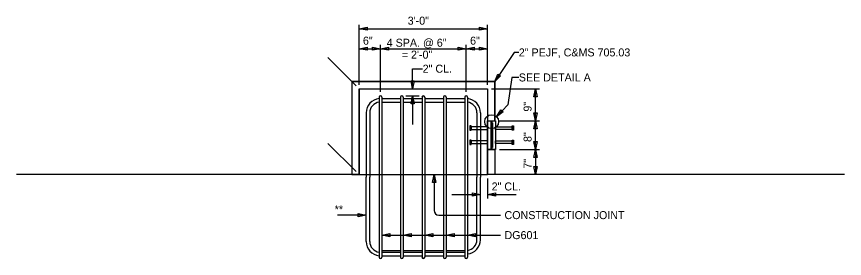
# Model space of a CAD drawing. Extents: x 1542883 to 1543620, y 586895 to 587380.
# Drawn here: x 1543043.59 to 1543058.08, y 587131.11 to 587135.34 of the extents above; entities that cross this region are included whole.
import ezdxf

# ---------------------------------------------------------------- set-up
doc = ezdxf.new("R2010")
doc.units = 0
for name, color, linetype in [('BR_P_Dia_Stl_Det', 7, 'Continuous'), ('BR_P_Gen_Text', 7, 'Continuous'), ('ST_Details', 7, 'Continuous'), ('ST_Text', 7, 'Continuous')]:
    doc.layers.add(name, color=color, linetype=linetype)

msp = doc.modelspace()

# ---------------------------------------------------------------- linework, layer by layer
at = {"layer": 'BR_P_Dia_Stl_Det'}
for p, q in [((1543049.582, 587134.151), (1543049.582, 587135.201)), ((1543049.582, 587135.131), (1543051.832, 587135.131)), ((1543051.832, 587134.151), (1543051.832, 587135.201)), ((1543049.957, 587134.026), (1543049.957, 587134.851)), ((1543051.457, 587134.026), (1543051.457, 587134.851)), ((1543049.582, 587134.781), (1543049.957, 587134.781)), ((1543049.957, 587134.781), (1543051.457, 587134.781)), ((1543051.457, 587134.781), (1543051.832, 587134.781)), ((1543049.533, 587134.13), (1543049.038, 587134.625)), ((1543050.52, 587134.081), (1543050.52, 587134.431)), ((1543050.52, 587134.431), (1543050.695, 587134.431)), ((1543052.257, 587134.278), (1543052.187, 587133.801)), ((1543052.378, 587134.278), (1543052.257, 587134.278)), ((1543049.457, 587134.206), (1543049.457, 587132.581)), ((1543049.457, 587134.206), (1543051.957, 587134.206)), ((1543051.957, 587134.206), (1543051.957, 587133.518)), ((1543049.582, 587134.081), (1543051.832, 587134.081)), ((1543049.582, 587134.081), (1543049.582, 587132.581)), ((1543051.832, 587134.081), (1543051.832, 587132.581)), ((1543051.902, 587134.081), (1543052.741, 587134.081)), ((1543052.671, 587133.518), (1543052.671, 587134.081)), ((1543049.934, 587133.932), (1543049.934, 587131.136)), ((1543049.981, 587133.932), (1543049.981, 587131.136)), ((1543049.981, 587133.909), (1543050.309, 587133.909)), ((1543049.981, 587133.847), (1543050.309, 587133.847)), ((1543050.309, 587133.932), (1543050.309, 587131.136)), ((1543050.356, 587133.932), (1543050.356, 587131.136)), ((1543050.356, 587133.909), (1543050.684, 587133.909)), ((1543050.356, 587133.847), (1543050.684, 587133.847)), ((1543050.402, 587133.956), (1543050.637, 587133.956)), ((1543050.52, 587133.956), (1543050.52, 587133.456)), ((1543050.684, 587133.932), (1543050.684, 587131.136)), ((1543050.731, 587133.932), (1543050.731, 587131.136)), ((1543050.731, 587133.909), (1543051.059, 587133.909)), ((1543050.731, 587133.847), (1543051.059, 587133.847)), ((1543051.059, 587133.932), (1543051.059, 587131.136)), ((1543051.106, 587133.932), (1543051.106, 587131.136)), ((1543051.106, 587133.909), (1543051.434, 587133.909)), ((1543051.106, 587133.847), (1543051.434, 587133.847)), ((1543051.434, 587133.932), (1543051.434, 587131.136)), ((1543051.481, 587133.932), (1543051.481, 587131.136)), ((1543052.187, 587133.801), (1543051.987, 587133.592)), ((1543049.707, 587133.659), (1543049.707, 587132.534)), ((1543049.77, 587133.659), (1543049.77, 587132.534)), ((1543051.645, 587133.659), (1543051.645, 587132.534)), ((1543051.707, 587133.659), (1543051.707, 587132.534)), ((1543051.908, 587133.487), (1543051.908, 587133.518)), ((1543052.041, 587133.518), (1543052.741, 587133.518)), ((1543052.671, 587133.018), (1543052.671, 587133.518)), ((1543049.533, 587132.63), (1543049.038, 587133.125)), ((1543051.908, 587133.05), (1543051.908, 587133.018)), ((1543051.957, 587133.018), (1543051.957, 587132.581)), ((1543052.041, 587133.018), (1543052.741, 587133.018)), ((1543052.671, 587133.018), (1543052.671, 587132.581)), ((1543049.582, 587132.581), (1543043.59, 587132.581)), ((1543049.582, 587132.581), (1543051.832, 587132.581)), ((1543049.707, 587131.409), (1543049.707, 587132.534)), ((1543049.77, 587131.409), (1543049.77, 587132.534)), ((1543050.895, 587132.581), (1543050.895, 587131.953)), ((1543051.645, 587131.44), (1543051.645, 587132.534)), ((1543051.707, 587131.44), (1543051.707, 587132.534)), ((1543058.075, 587132.581), (1543051.832, 587132.581)), ((1543051.832, 587132.511), (1543051.832, 587132.161)), ((1543051.207, 587132.231), (1543051.707, 587132.231)), ((1543051.832, 587132.231), (1543052.332, 587132.231)), ((1543049.707, 587131.87), (1543049.207, 587131.87)), ((1543050.978, 587131.87), (1543052.057, 587131.87)), ((1543049.981, 587131.52), (1543052.057, 587131.52)), ((1543049.981, 587131.253), (1543050.309, 587131.253)), ((1543049.981, 587131.222), (1543050.309, 587131.222)), ((1543050.356, 587131.253), (1543050.684, 587131.253)), ((1543050.356, 587131.222), (1543050.684, 587131.222)), ((1543050.731, 587131.253), (1543051.059, 587131.253)), ((1543050.731, 587131.222), (1543051.059, 587131.222)), ((1543051.106, 587131.253), (1543051.434, 587131.253)), ((1543051.106, 587131.222), (1543051.434, 587131.222)), ((1543049.981, 587131.159), (1543050.309, 587131.159)), ((1543050.356, 587131.159), (1543050.684, 587131.159)), ((1543050.731, 587131.159), (1543051.059, 587131.159)), ((1543051.106, 587131.159), (1543051.434, 587131.159))]:
    msp.add_line(p, q, dxfattribs=at)
for points in [[(1543049.722, 587135.159), (1543049.722, 587135.103), (1543049.582, 587135.131)], [(1543051.692, 587135.103), (1543051.692, 587135.159), (1543051.832, 587135.131)], [(1543049.722, 587134.809), (1543049.722, 587134.753), (1543049.582, 587134.781)], [(1543049.817, 587134.753), (1543049.817, 587134.809), (1543049.957, 587134.781)], [(1543050.097, 587134.809), (1543050.097, 587134.753), (1543049.957, 587134.781)], [(1543051.317, 587134.753), (1543051.317, 587134.809), (1543051.457, 587134.781)], [(1543051.597, 587134.809), (1543051.597, 587134.753), (1543051.457, 587134.781)], [(1543051.692, 587134.753), (1543051.692, 587134.809), (1543051.832, 587134.781)], [(1543052.012, 587134.338), (1543052.059, 587134.307), (1543051.957, 587134.206)], [(1543049.457, 587132.581), (1543049.582, 587132.581), (1543049.582, 587134.081), (1543051.832, 587134.081), (1543051.832, 587133.518), (1543051.957, 587133.518), (1543051.957, 587134.206), (1543049.457, 587134.206)], [(1543050.492, 587134.221), (1543050.548, 587134.221), (1543050.52, 587134.081)], [(1543052.699, 587133.941), (1543052.643, 587133.941), (1543052.671, 587134.081)], [(1543050.548, 587133.816), (1543050.492, 587133.816), (1543050.52, 587133.956)], [(1543052.063, 587133.713), (1543052.104, 587133.674), (1543051.987, 587133.592)], [(1543052.643, 587133.658), (1543052.699, 587133.658), (1543052.671, 587133.518)], [(1543051.543, 587133.432), (1543051.52, 587133.432), (1543051.52, 587133.354), (1543051.543, 587133.354)], [(1543051.832, 587133.417), (1543051.543, 587133.417), (1543051.543, 587133.37), (1543051.832, 587133.37)], [(1543051.832, 587133.518), (1543051.895, 587133.518), (1543051.895, 587133.018), (1543051.832, 587133.018)], [(1543051.895, 587133.518), (1543051.908, 587133.518), (1543051.908, 587133.487), (1543051.901, 587133.487), (1543051.901, 587133.503), (1543051.895, 587133.503)], [(1543051.895, 587133.503), (1543051.901, 587133.503), (1543051.901, 587133.034), (1543051.895, 587133.034)], [(1543051.901, 587133.487), (1543051.916, 587133.487), (1543051.916, 587133.05), (1543051.901, 587133.05)], [(1543051.971, 587133.417), (1543052.26, 587133.417), (1543052.26, 587133.37), (1543051.971, 587133.37)], [(1543052.26, 587133.432), (1543052.283, 587133.432), (1543052.283, 587133.354), (1543052.26, 587133.354)], [(1543052.699, 587133.378), (1543052.643, 587133.378), (1543052.671, 587133.518)], [(1543051.543, 587133.182), (1543051.52, 587133.182), (1543051.52, 587133.104), (1543051.543, 587133.104)], [(1543051.832, 587133.167), (1543051.543, 587133.167), (1543051.543, 587133.12), (1543051.832, 587133.12)], [(1543051.971, 587133.167), (1543052.26, 587133.167), (1543052.26, 587133.12), (1543051.971, 587133.12)], [(1543052.26, 587133.182), (1543052.283, 587133.182), (1543052.283, 587133.104), (1543052.26, 587133.104)], [(1543052.643, 587133.158), (1543052.699, 587133.158), (1543052.671, 587133.018)], [(1543051.832, 587132.581), (1543051.832, 587133.018), (1543051.957, 587133.018), (1543051.957, 587132.581)], [(1543052.699, 587132.878), (1543052.643, 587132.878), (1543052.671, 587133.018)], [(1543052.643, 587132.721), (1543052.699, 587132.721), (1543052.671, 587132.581)], [(1543050.923, 587132.441), (1543050.867, 587132.441), (1543050.895, 587132.581)], [(1543051.567, 587132.203), (1543051.567, 587132.259), (1543051.707, 587132.231)], [(1543051.972, 587132.259), (1543051.972, 587132.203), (1543051.832, 587132.231)], [(1543049.567, 587131.842), (1543049.567, 587131.898), (1543049.707, 587131.87)], [(1543050.121, 587131.548), (1543050.121, 587131.492), (1543049.981, 587131.52)], [(1543050.496, 587131.548), (1543050.496, 587131.492), (1543050.356, 587131.52)], [(1543050.871, 587131.548), (1543050.871, 587131.492), (1543050.731, 587131.52)], [(1543051.246, 587131.548), (1543051.246, 587131.492), (1543051.106, 587131.52)], [(1543051.621, 587131.548), (1543051.621, 587131.492), (1543051.481, 587131.52)]]:
    msp.add_lwpolyline(points, close=True, dxfattribs=at)
for points in [[(1543052.378, 587134.716), (1543052.299, 587134.716), (1543051.957, 587134.206)], [(1543051.908, 587133.487), (1543051.908, 587133.518), (1543051.971, 587133.518), (1543051.971, 587133.018), (1543051.908, 587133.018), (1543051.908, 587133.05)]]:
    msp.add_lwpolyline(points, dxfattribs=at)
msp.add_circle((1543051.903, 587133.505), 0.121, dxfattribs=at)
for centre, radius, start, end in [((1543049.957, 587133.659), 0.25, 95.3794, 180), ((1543049.957, 587133.659), 0.188, 97.1808, 180), ((1543049.957, 587133.932), 0.0234, 0, 180), ((1543050.332, 587133.932), 0.0234, 0, 180), ((1543050.707, 587133.932), 0.0234, 0, 180), ((1543051.082, 587133.932), 0.0234, 0, 180), ((1543051.457, 587133.932), 0.0234, 0, 180), ((1543051.457, 587133.659), 0.25, 360, 84.6206), ((1543051.457, 587133.659), 0.188, 0, 82.8192), ((1543050.978, 587131.953), 0.0833, 180, 270), ((1543049.957, 587131.409), 0.25, 180, 264.6206), ((1543049.957, 587131.409), 0.188, 180, 262.8192), ((1543051.457, 587131.44), 0.188, 277.1808, 360), ((1543051.457, 587131.44), 0.25, 275.3794, 360), ((1543049.957, 587131.136), 0.0234, 180, 0), ((1543050.332, 587131.136), 0.0234, 180, 0), ((1543050.707, 587131.136), 0.0234, 180, 0), ((1543051.082, 587131.136), 0.0234, 180, 0), ((1543051.457, 587131.136), 0.0234, 180, 0)]:
    msp.add_arc(centre, radius, start, end, dxfattribs=at)
at = {"layer": 'BR_P_Gen_Text'}
for points in [[(1543049.722, 587135.159), (1543049.722, 587135.103), (1543049.582, 587135.131)], [(1543051.692, 587135.103), (1543051.692, 587135.159), (1543051.832, 587135.131)], [(1543049.722, 587134.809), (1543049.722, 587134.753), (1543049.582, 587134.781)], [(1543049.817, 587134.753), (1543049.817, 587134.809), (1543049.957, 587134.781)], [(1543050.097, 587134.809), (1543050.097, 587134.753), (1543049.957, 587134.781)], [(1543051.317, 587134.753), (1543051.317, 587134.809), (1543051.457, 587134.781)], [(1543051.597, 587134.809), (1543051.597, 587134.753), (1543051.457, 587134.781)], [(1543051.692, 587134.753), (1543051.692, 587134.809), (1543051.832, 587134.781)], [(1543052.012, 587134.338), (1543052.059, 587134.307), (1543051.957, 587134.206)], [(1543050.492, 587134.221), (1543050.548, 587134.221), (1543050.52, 587134.081)], [(1543052.699, 587133.941), (1543052.643, 587133.941), (1543052.671, 587134.081)], [(1543050.548, 587133.816), (1543050.492, 587133.816), (1543050.52, 587133.956)], [(1543052.063, 587133.713), (1543052.104, 587133.674), (1543051.987, 587133.592)], [(1543052.643, 587133.658), (1543052.699, 587133.658), (1543052.671, 587133.518)], [(1543052.699, 587133.378), (1543052.643, 587133.378), (1543052.671, 587133.518)], [(1543052.643, 587133.158), (1543052.699, 587133.158), (1543052.671, 587133.018)], [(1543052.699, 587132.878), (1543052.643, 587132.878), (1543052.671, 587133.018)], [(1543052.643, 587132.721), (1543052.699, 587132.721), (1543052.671, 587132.581)], [(1543050.923, 587132.441), (1543050.867, 587132.441), (1543050.895, 587132.581)], [(1543051.567, 587132.203), (1543051.567, 587132.259), (1543051.707, 587132.231)], [(1543051.972, 587132.259), (1543051.972, 587132.203), (1543051.832, 587132.231)], [(1543049.567, 587131.842), (1543049.567, 587131.898), (1543049.707, 587131.87)], [(1543050.121, 587131.548), (1543050.121, 587131.492), (1543049.981, 587131.52)], [(1543050.496, 587131.548), (1543050.496, 587131.492), (1543050.356, 587131.52)], [(1543050.871, 587131.548), (1543050.871, 587131.492), (1543050.731, 587131.52)], [(1543051.246, 587131.548), (1543051.246, 587131.492), (1543051.106, 587131.52)], [(1543051.621, 587131.548), (1543051.621, 587131.492), (1543051.481, 587131.52)]]:
    msp.add_lwpolyline(points, close=True, dxfattribs=at)
at = {"layer": 'ST_Details'}
for p, q in [((1543049.582, 587134.151), (1543049.582, 587135.201)), ((1543049.582, 587135.131), (1543051.832, 587135.131)), ((1543051.832, 587134.151), (1543051.832, 587135.201)), ((1543049.957, 587134.026), (1543049.957, 587134.851)), ((1543051.457, 587134.026), (1543051.457, 587134.851)), ((1543049.582, 587134.781), (1543049.957, 587134.781)), ((1543049.957, 587134.781), (1543051.457, 587134.781)), ((1543051.457, 587134.781), (1543051.832, 587134.781)), ((1543049.533, 587134.13), (1543049.038, 587134.625)), ((1543050.52, 587134.081), (1543050.52, 587134.431)), ((1543050.52, 587134.431), (1543050.695, 587134.431)), ((1543052.257, 587134.278), (1543052.187, 587133.801)), ((1543052.378, 587134.278), (1543052.257, 587134.278)), ((1543049.457, 587134.206), (1543049.457, 587132.581)), ((1543049.457, 587134.206), (1543051.957, 587134.206)), ((1543051.957, 587134.206), (1543051.957, 587133.518)), ((1543049.582, 587134.081), (1543051.832, 587134.081)), ((1543049.582, 587134.081), (1543049.582, 587132.581)), ((1543051.832, 587134.081), (1543051.832, 587132.581)), ((1543051.902, 587134.081), (1543052.741, 587134.081)), ((1543052.671, 587133.518), (1543052.671, 587134.081)), ((1543049.934, 587133.932), (1543049.934, 587131.136)), ((1543049.981, 587133.932), (1543049.981, 587131.136)), ((1543049.981, 587133.909), (1543050.309, 587133.909)), ((1543049.981, 587133.847), (1543050.309, 587133.847)), ((1543050.309, 587133.932), (1543050.309, 587131.136)), ((1543050.356, 587133.932), (1543050.356, 587131.136)), ((1543050.356, 587133.909), (1543050.684, 587133.909)), ((1543050.356, 587133.847), (1543050.684, 587133.847)), ((1543050.402, 587133.956), (1543050.637, 587133.956)), ((1543050.52, 587133.956), (1543050.52, 587133.456)), ((1543050.684, 587133.932), (1543050.684, 587131.136)), ((1543050.731, 587133.932), (1543050.731, 587131.136)), ((1543050.731, 587133.909), (1543051.059, 587133.909)), ((1543050.731, 587133.847), (1543051.059, 587133.847)), ((1543051.059, 587133.932), (1543051.059, 587131.136)), ((1543051.106, 587133.932), (1543051.106, 587131.136)), ((1543051.106, 587133.909), (1543051.434, 587133.909)), ((1543051.106, 587133.847), (1543051.434, 587133.847)), ((1543051.434, 587133.932), (1543051.434, 587131.136)), ((1543051.481, 587133.932), (1543051.481, 587131.136)), ((1543052.187, 587133.801), (1543051.987, 587133.592)), ((1543049.707, 587133.659), (1543049.707, 587132.534)), ((1543049.77, 587133.659), (1543049.77, 587132.534)), ((1543051.645, 587133.659), (1543051.645, 587132.534)), ((1543051.707, 587133.659), (1543051.707, 587132.534)), ((1543051.908, 587133.487), (1543051.908, 587133.518)), ((1543052.041, 587133.518), (1543052.741, 587133.518)), ((1543052.671, 587133.018), (1543052.671, 587133.518)), ((1543049.533, 587132.63), (1543049.038, 587133.125)), ((1543051.908, 587133.05), (1543051.908, 587133.018)), ((1543051.957, 587133.018), (1543051.957, 587132.581)), ((1543052.041, 587133.018), (1543052.741, 587133.018)), ((1543052.671, 587133.018), (1543052.671, 587132.581)), ((1543049.582, 587132.581), (1543043.59, 587132.581)), ((1543049.582, 587132.581), (1543051.832, 587132.581)), ((1543049.707, 587131.409), (1543049.707, 587132.534)), ((1543049.77, 587131.409), (1543049.77, 587132.534)), ((1543050.895, 587132.581), (1543050.895, 587131.953)), ((1543051.645, 587131.44), (1543051.645, 587132.534)), ((1543051.707, 587131.44), (1543051.707, 587132.534)), ((1543058.075, 587132.581), (1543051.832, 587132.581)), ((1543051.832, 587132.511), (1543051.832, 587132.161)), ((1543051.207, 587132.231), (1543051.707, 587132.231)), ((1543051.832, 587132.231), (1543052.332, 587132.231)), ((1543049.707, 587131.87), (1543049.207, 587131.87)), ((1543050.978, 587131.87), (1543052.057, 587131.87)), ((1543049.981, 587131.52), (1543052.057, 587131.52)), ((1543049.981, 587131.253), (1543050.309, 587131.253)), ((1543049.981, 587131.222), (1543050.309, 587131.222)), ((1543050.356, 587131.253), (1543050.684, 587131.253)), ((1543050.356, 587131.222), (1543050.684, 587131.222)), ((1543050.731, 587131.253), (1543051.059, 587131.253)), ((1543050.731, 587131.222), (1543051.059, 587131.222)), ((1543051.106, 587131.253), (1543051.434, 587131.253)), ((1543051.106, 587131.222), (1543051.434, 587131.222)), ((1543049.981, 587131.159), (1543050.309, 587131.159)), ((1543050.356, 587131.159), (1543050.684, 587131.159)), ((1543050.731, 587131.159), (1543051.059, 587131.159)), ((1543051.106, 587131.159), (1543051.434, 587131.159))]:
    msp.add_line(p, q, dxfattribs=at)
for points in [[(1543052.378, 587134.716), (1543052.299, 587134.716), (1543051.957, 587134.206)], [(1543051.908, 587133.487), (1543051.908, 587133.518), (1543051.971, 587133.518), (1543051.971, 587133.018), (1543051.908, 587133.018), (1543051.908, 587133.05)]]:
    msp.add_lwpolyline(points, dxfattribs=at)
for points in [[(1543049.457, 587132.581), (1543049.582, 587132.581), (1543049.582, 587134.081), (1543051.832, 587134.081), (1543051.832, 587133.518), (1543051.957, 587133.518), (1543051.957, 587134.206), (1543049.457, 587134.206)], [(1543051.543, 587133.432), (1543051.52, 587133.432), (1543051.52, 587133.354), (1543051.543, 587133.354)], [(1543051.832, 587133.417), (1543051.543, 587133.417), (1543051.543, 587133.37), (1543051.832, 587133.37)], [(1543051.832, 587133.518), (1543051.895, 587133.518), (1543051.895, 587133.018), (1543051.832, 587133.018)], [(1543051.895, 587133.518), (1543051.908, 587133.518), (1543051.908, 587133.487), (1543051.901, 587133.487), (1543051.901, 587133.503), (1543051.895, 587133.503)], [(1543051.895, 587133.503), (1543051.901, 587133.503), (1543051.901, 587133.034), (1543051.895, 587133.034)], [(1543051.901, 587133.487), (1543051.916, 587133.487), (1543051.916, 587133.05), (1543051.901, 587133.05)], [(1543051.971, 587133.417), (1543052.26, 587133.417), (1543052.26, 587133.37), (1543051.971, 587133.37)], [(1543052.26, 587133.432), (1543052.283, 587133.432), (1543052.283, 587133.354), (1543052.26, 587133.354)], [(1543051.543, 587133.182), (1543051.52, 587133.182), (1543051.52, 587133.104), (1543051.543, 587133.104)], [(1543051.832, 587133.167), (1543051.543, 587133.167), (1543051.543, 587133.12), (1543051.832, 587133.12)], [(1543051.971, 587133.167), (1543052.26, 587133.167), (1543052.26, 587133.12), (1543051.971, 587133.12)], [(1543052.26, 587133.182), (1543052.283, 587133.182), (1543052.283, 587133.104), (1543052.26, 587133.104)], [(1543051.832, 587132.581), (1543051.832, 587133.018), (1543051.957, 587133.018), (1543051.957, 587132.581)]]:
    msp.add_lwpolyline(points, close=True, dxfattribs=at)
msp.add_circle((1543051.903, 587133.505), 0.121, dxfattribs=at)
for centre, radius, start, end in [((1543049.957, 587133.659), 0.25, 95.3794, 180), ((1543049.957, 587133.659), 0.188, 97.1808, 180), ((1543049.957, 587133.932), 0.0234, 0, 180), ((1543050.332, 587133.932), 0.0234, 0, 180), ((1543050.707, 587133.932), 0.0234, 0, 180), ((1543051.082, 587133.932), 0.0234, 0, 180), ((1543051.457, 587133.932), 0.0234, 0, 180), ((1543051.457, 587133.659), 0.25, 360, 84.6206), ((1543051.457, 587133.659), 0.188, 0, 82.8192), ((1543050.978, 587131.953), 0.0833, 180, 270), ((1543049.957, 587131.409), 0.25, 180, 264.6206), ((1543049.957, 587131.409), 0.188, 180, 262.8192), ((1543051.457, 587131.44), 0.188, 277.1808, 360), ((1543051.457, 587131.44), 0.25, 275.3794, 360), ((1543049.957, 587131.136), 0.0234, 180, 0), ((1543050.332, 587131.136), 0.0234, 180, 0), ((1543050.707, 587131.136), 0.0234, 180, 0), ((1543051.082, 587131.136), 0.0234, 180, 0), ((1543051.457, 587131.136), 0.0234, 180, 0)]:
    msp.add_arc(centre, radius, start, end, dxfattribs=at)

# ---------------------------------------------------------------- texts
at = {"layer": 'BR_P_Dia_Stl_Det'}
for s, p in [('3\'-0"', (1543050.433, 587135.201)), ('6"', (1543049.65, 587134.851)), ('6"', (1543051.525, 587134.851)), ('4 SPA. @ 6"', (1543050.066, 587134.815)), ('= 2\'-0"', (1543050.33, 587134.607)), ('2" PEJF, C&MS 705.03', (1543052.378, 587134.646)), ('2" CL.', (1543050.695, 587134.361)), ('SEE DETAIL A', (1543052.378, 587134.208)), ('2" CL.', (1543051.902, 587132.301)), ('**', (1543049.156, 587131.902)), ('CONSTRUCTION JOINT', (1543052.127, 587131.8)), ('DG601', (1543052.127, 587131.45))]:
    msp.add_text(s, height=0.14, dxfattribs=at).set_placement(p)
for s, p in [('9"', (1543052.601, 587133.68)), ('8"', (1543052.601, 587133.149)), ('7"', (1543052.601, 587132.682))]:
    msp.add_text(s, height=0.14, rotation=90, dxfattribs=at).set_placement(p)
at = {"layer": 'ST_Text'}
for s, p in [('3\'-0"', (1543050.433, 587135.201)), ('6"', (1543049.65, 587134.851)), ('6"', (1543051.525, 587134.851)), ('4 SPA. @ 6"', (1543050.066, 587134.815)), ('= 2\'-0"', (1543050.33, 587134.607)), ('2" PEJF, C&MS 705.03', (1543052.378, 587134.646)), ('2" CL.', (1543050.695, 587134.361)), ('SEE DETAIL A', (1543052.378, 587134.208)), ('2" CL.', (1543051.902, 587132.301)), ('**', (1543049.156, 587131.902)), ('CONSTRUCTION JOINT', (1543052.127, 587131.8)), ('DG601', (1543052.127, 587131.45))]:
    msp.add_text(s, height=0.14, dxfattribs=at).set_placement(p)
for s, p in [('9"', (1543052.601, 587133.68)), ('8"', (1543052.601, 587133.149)), ('7"', (1543052.601, 587132.682))]:
    msp.add_text(s, height=0.14, rotation=90, dxfattribs=at).set_placement(p)

doc.saveas('drawing.dxf')
